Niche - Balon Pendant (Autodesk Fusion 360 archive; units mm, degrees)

design "Encalmo Grand" references "Encalmo Grand", "Niche - Chief Architect - Luxe Single Pendant Cordset", "Luxe Single Pendant Cordset - 4ft Standard"
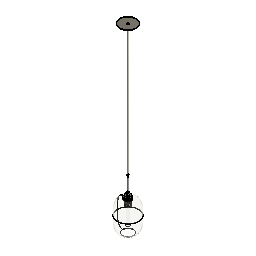
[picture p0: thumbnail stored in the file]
external_derived "ExternalDerived1" bodies "Encalmo Grand", "Encalmo Grand (1)"
external_derived "ExternalDerived2" bodies "Socket Body", "Shade Ring", "Shade Ring +Collar", "Socket", "Body1", "Metal Strain Relief", "Fabric Cord (1)", "Stem (Threaded)"
move "Move1"
external_derived "ExternalDerived3" bodies "T9-Bulb"
move "Move2"
scale "Scale1"
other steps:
derived_base_feature "Derived Base Feature1" bodies "Encalmo Grand", "Encalmo Grand (1)"
derived_base_feature "Derived Base Feature2" bodies "Socket Body", "Shade Ring", "Shade Ring +Collar", "Socket", "Body1", "Metal Strain Relief", "Fabric Cord (1)", "Stem (Threaded)"
derived_base_feature "Derived Base Feature3" bodies "T9-Bulb"
named bodies: "Encalmo Grand", "Encalmo Grand (1)", "Socket Body", "Shade Ring", "Shade Ring +Collar", "Socket", "Body1", "Metal Strain Relief", "Fabric Cord (1)", "Stem (Threaded)", "Cap (Threaded)", "5M Set Screw", "T9-Bulb"

design "Luxe Single Pendant Cordset - 4ft Standard" references "Luxe Canopy - Single Pendant Cordset"
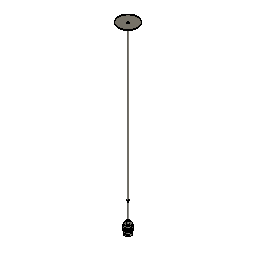
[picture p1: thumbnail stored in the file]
external_derived "ExternalDerived2" bodies "Cap (Threaded)"
move "Move1"
move "Move2"
offset_faces "OffsetFaces1" distance 1051.56
move "Move3"
move "Move4"
move "Move5"
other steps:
derived_base_feature "Derived Base Feature9" bodies "Socket Body", "Shade Ring", "Shade Ring +Collar", "Socket"
derived_base_feature "Derived Base Feature10" bodies "Body1"
derived_base_feature "Derived Base Feature12" bodies "Metal Strain Relief"
derived_base_feature "Derived Base Feature13" bodies "Fabric Cord (1)"
derived_base_feature "Derived Base Feature14" bodies "Stem (Threaded)"
derived_base_feature "Derived Base Feature15" bodies "Cap 9Threaded)", "Cap (Threaded)"
named bodies: "Socket Body", "Shade Ring", "Shade Ring +Collar", "Socket", "Metal Strain Relief", "Fabric Cord (1)", "Stem (Threaded)", "Cap 9Threaded)", "Body1", "Cap (Threaded)", "5M Set Screw"

design "Encalmo Grand" references "Niche_Encalmo_Grand_Single_Pendant"
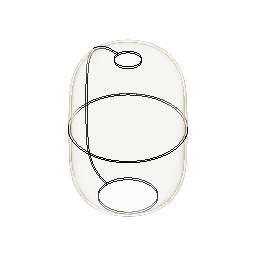
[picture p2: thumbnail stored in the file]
external_derived "ExternalDerived1" bodies "Encalmo Grand"
work_plane "WorkPlane1" AlongDistance -124.2212
split "Split1" bodies "Encalmo Grand (1)"
fillet "Fillet1" radius 0.0254
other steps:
derived_base_feature "Derived Base Feature" bodies "Encalmo Grand"
named bodies: "Encalmo Grand", "Encalmo Grand (1)"

design "Luxe Canopy - Single Pendant Cordset" references "Canopy Mounting Bar Screw", "Canopy Mounting Bar", "M5 Set Screw", "Plastic Strain Relief", "Luxe Cordset"
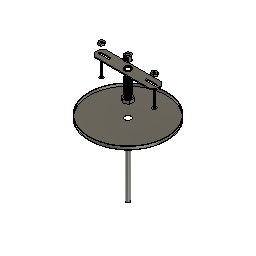
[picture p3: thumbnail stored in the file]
sketch "Sketch1" plane through (0, 0, 0) normal (0, 0, 1) x axis (1, 0, 0)
  circle C1 centre (0, 0) radius 63.5
  point P1 (0, 0)
  point P2 (0, 0)
  coincident P1 P2
  dimension "d1" diameter C1 = 127
extrude "Extrude1" new body sketch "Sketch1" along normal blind 5.08
shell "Shell1" innerThickness 0.762
hole "Hole1" HoleDepth 35.56 HoleDiameter 10.16 TipAngle 118
component_from_bodies "Body->Comp1"
component_insert "Component Insert1"
component_insert "Component Insert2"
component_insert "Component Insert3"
sketch "Sketch2" plane through (0, 0, 0) normal (0, 0, 1) x axis (1, 0, 0)
  circle C1 centre (0, 0) radius 3.175
  point P1 (0, 0)
  point P2 (0, 0)
  coincident P1 P2
  dimension "d8" diameter C1 = 6.35
extrude "Extrude2" new body sketch "Sketch2" along normal blind 127 and against normal blind 127 bodies "Fabric Cord"
component_insert "Component Insert4"
component_insert "Component Insert5"
position "Position1"
sketch "Sketch3" plane through (0, 0, 0.762) normal (0, 0, 1) x axis (-1, 0, 0)
  circle C1 centre (-0.0475, 0.2257) radius 5.08
  circle C2 centre (0, 0) radius 62.738
  circle C3 centre (0, 0) radius 4.826
  concentric C2 C3
  dimension "d13" diameter C3 = 9.652
extrude "Extrude3" new body sketch "Sketch3" profile of C3 along normal blind 25.4 bodies "Threaded Nipple"
shell "Shell2" innerThickness 1.27
thread "Thread1"
sketch "Sketch5" plane through (0, 0, 127) normal (0, 0, 1) x axis (-1, 0, 0)
  line L1 (-6.8191, 3.937) -> (0, 7.874)
  line L2 (-6.8191, -3.937) -> (-6.8191, 3.937)
  line L3 (0, -7.874) -> (-6.8191, -3.937)
  line L4 (6.8191, -3.937) -> (0, -7.874)
  line L5 (6.8191, 3.937) -> (6.8191, -3.937)
  line L6 (0, 7.874) -> (6.8191, 3.937)
  circle C1 centre (0, 0) radius 3.175
  point P2 (0, 0)
  point P9 (0, 0)
  point P3 (0, 7.874)
  coincident P2 P9
  dimension "d20" distance P3 P9 = 7.874
extrude "Extrude4" new body sketch "Sketch5" along normal blind 5.08 bodies "Hex Nut"
move "Move1"
thread "Thread2"
move "Move2" TranslateX 0 TranslateY 0 TranslateZ -55.88
move "Move3" TranslateX 0 TranslateY 0 TranslateZ 60.96
position "Position2"
sketch "Sketch6" plane through (0, 0, 0) normal (0, 0, 1) x axis (1, 0, 0)
  circle C1 centre (0, 0) radius 9.525
  point P1 (0, 0)
  point P2 (0, 0)
  coincident P1 P2
  dimension "d29" diameter C1 = 19.05
extrude "Extrude5" new body sketch "Sketch6" along normal blind 16.129 bodies "Metal Strain Relief"
move "Move4" TranslateX 0 TranslateY 0 TranslateZ -86.36
hole "Hole2" HoleDepth 10.16 HoleDiameter 5.08 TipAngle 118
hole "Hole3" HoleDepth 4.064 HoleDiameter 7.62 TipAngle 180
hole "Hole4" HoleDepth 12.192 HoleDiameter 9.144 TipAngle 180
thread "Thread3" ThreadOffset 0 ThreadLength 6.096
move "Move1" TranslateX 0 TranslateY 0 TranslateZ 68.58
move "Move5" TranslateX 0 TranslateY 0 TranslateZ 138.43
component_insert "Component Insert6"
external_derived "ExternalDerived1" bodies "5M Set Screw"
move "Move6" TranslateX 0 TranslateY 0 TranslateZ -185.42
copy_paste_bodies "CopyPasteBodies1"
move "Move7" TranslateX 0 TranslateY 0 TranslateZ -12.7
offset_faces "OffsetFaces1" distance -152.4
move "Move8"
component_from_bodies "Body->Comp2"
component_from_bodies "Body->Comp3"
component_from_bodies "Body->Comp4"
component_from_bodies "Body->Comp5"
hole "Hole1" HoleDepth 25.4 HoleDiameter 6.35 TipAngle 180
sketch "Sketch7" plane through (0, 0, 0) normal (0, 0, 1) x axis (1, 0, 0)
  line L1 (49.784, 3.9595) -> (52.07, 0)
  line L2 (45.212, 3.9595) -> (49.784, 3.9595)
  line L3 (42.926, 0) -> (45.212, 3.9595)
  line L4 (45.212, -3.9595) -> (42.926, 0)
  line L5 (49.784, -3.9595) -> (45.212, -3.9595)
  line L6 (52.07, 0) -> (49.784, -3.9595)
  point P2 (52.07, 0)
  point P8 (47.498, 0)
  dimension "d63" distance P2 P8 = 4.572
extrude "Extrude6" new body sketch "Sketch7" along normal blind 3.175 bodies "Mounting Hex Nut"
hole "Hole5" HoleDepth 25.4 HoleDiameter 3.81 TipAngle 180
thread "Thread4"
move "Move9"
component_from_bodies "Body->Comp6"
copy_paste "CopyPaste1"
move "Move10"
derived_base_feature "Derived Base Feature3" bodies "Stem (Threaded)", "Cap 9Threaded)"
move "Move11"
component_from_bodies "Body->Comp7"
component_from_bodies "Body->Comp8"
component_from_bodies "Body->Comp9"
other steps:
base_feature "Base Feature1"
base_feature "Base Feature1" bodies "Stem (Threaded)"
base_feature "Base Feature1" bodies "Cap 9Threaded)"
base_feature "Base Feature1" bodies "Fabric Cord"
base_feature "Base Feature1" bodies "Metal Strain Relief"
base_feature "Base Feature1" bodies "Mounting Hex Nut"
base_feature "Base Feature1" bodies "Hex Nut"
base_feature "Base Feature1" bodies "Fabric Cord (1)"
base_feature "Base Feature1" bodies "Threaded Nipple"
derived_base_feature "Derived Base Feature1" bodies "Socket Body", "Shade Ring", "Shade Ring +Collar", "Socket", "Rigid Stem"
derived_base_feature "Derived Base Feature2" bodies "5M Set Screw"
base_feature "Base Feature1" bodies "Fabric Cord", "Fabric Cord (1)"
create_component "CreateComponent1"
remove_body "RemoveBody1"
create_component "CreateComponent2"
remove_body "RemoveBody2"
create_component "CreateComponent3"
remove_body "RemoveBody3"
create_component "CreateComponent4"
remove_body "RemoveBody4"
create_component "CreateComponent5"
remove_body "RemoveBody5"
create_component "CreateComponent6"
remove_body "RemoveBody6"
create_component "CreateComponent7"
remove_body "RemoveBody7"
create_component "CreateComponent8"
remove_body "RemoveBody8"
create_component "CreateComponent9"
remove_body "RemoveBody9"
named bodies: "Fabric Cord", "Threaded Nipple", "Hex Nut", "Metal Strain Relief", "Socket Body", "Shade Ring", "Shade Ring +Collar", "Socket", "Rigid Stem", "5M Set Screw", "Fabric Cord (1)", "Mounting Hex Nut", "Stem (Threaded)", "Cap 9Threaded)"

design "M5 Set Screw"
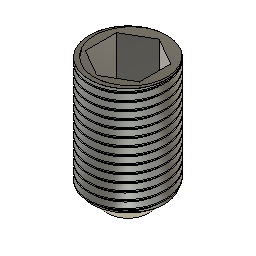
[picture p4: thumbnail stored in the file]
sketch "Sketch1" plane through (0, 0, 0) normal (0, 0, 1) x axis (1, 0, 0)
  circle C1 centre (0, 0) radius 2.5
  point P1 (0, 0)
  point P2 (0, 0)
  coincident P1 P2
  dimension "d1" diameter C1 = 5
extrude "Extrude1" new body sketch "Sketch1" along normal blind 8
sketch "Sketch2" plane through (0, 0, 8) normal (0, 0, 1) x axis (-1, 0, 0)
  line L1 (-1.7321, 1) -> (0, 2)
  line L2 (-1.7321, -1) -> (-1.7321, 1)
  line L3 (0, -2) -> (-1.7321, -1)
  line L4 (1.7321, -1) -> (0, -2)
  line L5 (1.7321, 1) -> (1.7321, -1)
  line L6 (0, 2) -> (1.7321, 1)
  circle C1 centre (0, 0) radius 2.5
  point P2 (0, 0)
  point P9 (0, 0)
  coincident P2 P9
extrude "Extrude2" cut sketch "Sketch2" profile of L1 L2 L3 L4 L5 L6 against normal blind 3
thread "Thread1" ThreadOffset 0.99 ThreadLength 7
chamfer "Chamfer1" distance 1.15

design "Luxe Cordset" references "M5 Set Screw"
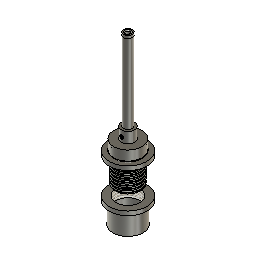
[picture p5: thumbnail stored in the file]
sketch "Sketch1" plane through (0, 0, 0) normal (0, 0, 1) x axis (1, 0, 0)
  circle C1 centre (0, 0) radius 20.6
  point P1 (0, 0)
  point P2 (0, 0)
  coincident P1 P2
  dimension "d11" diameter C1 = 41.2
extrude "Extrude1" new body sketch "Sketch1" along normal blind 14 bodies "Socket Body"
sketch "Sketch2" plane through (0, 0, 14) normal (0, 0, 1) x axis (-1, 0, 0)
  circle C1 centre (0, 0) radius 20.6
  circle C2 centre (0, 0) radius 9.6
  concentric C1 C2
  dimension "d3" diameter C2 = 19.2
extrude "Extrude2" add sketch "Sketch2" profile of C2 along normal blind 15.75
sketch "Sketch3" plane through (0, 0, 29.75) normal (0, 0, 1) x axis (-1, 0, 0)
  circle C1 centre (0, 0) radius 9.6
  circle C2 centre (0, 0) radius 5.75
  concentric C1 C2
  dimension "d6" diameter C2 = 11.5
extrude "Extrude3" new body sketch "Sketch3" profile of C2 along normal blind 114 bodies "Rigid Stem"
move "Move1"
sketch "Sketch4" plane through (0, 0, 203.75) normal (0, 0, 1) x axis (-1, 0, 0)
  circle C1 centre (0, 0) radius 5.75
  circle C2 centre (0, 0) radius 27.5
  dimension "d10" diameter C2 = 55
extrude "Extrude4" new body sketch "Sketch4" profile of C2 along normal blind 6 bodies "Shade Ring"
hole "Hole1" HoleDepth 25 HoleDiameter 42.75 TipAngle 118
sketch "Sketch5" plane through (0, 0, 0) normal (0, 0, 1) x axis (1, 0, 0)
  circle C1 centre (0, 0) radius 22
  point P1 (0, 0)
  point P2 (0, 0)
  coincident P1 P2
  dimension "d18" diameter C1 = 44
move "Move2"
copy_paste_bodies "CopyPasteBodies1"
move "Move3"
sketch "Sketch6" plane through (0, 0, 60) normal (0, 0, -1) x axis (1, 0, 0)
  circle C1 centre (0, 0) radius 20.6
  circle C2 centre (0, 0) radius 21.375
  circle C3 centre (0, 0) radius 20
  concentric C1 C2
  concentric C1 C3
  dimension "d21" diameter C2 = 42.75
  dimension "d24" diameter C3 = 40
cylinder_primitive "CylinderPrimitive1" Height 8 Diameter 42.75
thread "Thread1"
thread "Thread3"
hole "Hole2" HoleDepth 18 HoleDiameter 39 TipAngle 180
move "Move4"
move "Move5"
move "Move6"
hole "Hole3" HoleDepth 114 HoleDiameter 7.6 TipAngle 180
derived_base_feature "Derived Base Feature" bodies "Socket"
move "Move7"
scale "Scale1" ScaleX 1.2 ScaleY 1.2
move "Move8"
sketch "Sketch8" plane through (0, 0, -23.9827) normal (0, 0, -1) x axis (1, 0, 0)
  circle C1 centre (0, -0.036) radius 27.5
  circle C2 centre (0, -0.036) radius 22
  circle C3 centre (0, -0.036) radius 19.5
  dimension "d36" diameter C2 = 44
  dimension "d42" = -2.5
extrude "Extrude7" add sketch "Sketch8" profile of C2 C3 along normal blind 30
offset_faces "OffsetFaces1" distance 2.75
offset_faces "OffsetFaces2" distance -9
thread "Thread2"
move "Move9"
move "Move10"
move "Move11"
scale "Scale2" ScaleZ 1.2
move "Move12"
move "Move13"
move "Move14"
move "Move15"
move "Move16"
split_face "SplitFace1"
move "Move17"
move "Move18"
move "Move19"
move "Move20"
move "Move21"
move "Move22"
move "Move23"
move "Move24"
move "Move25"
move "Move26"
move "Move27"
thread "Thread4"
move "Move28"
move "Move29"
move "Move30"
hole "Hole4" HoleDepth 21 HoleDiameter 39.35 TipAngle 180
hole "Hole5" HoleDepth 9 HoleDiameter 5 TipAngle 180
move "Move31"
move "Move32"
hole "Hole6" HoleDepth 20 HoleDiameter 10 TipAngle 180
move_face "MoveFace3"
move "Move33"
move "Move34"
move "Move35"
move "Move36"
move "Move37"
thread "Thread5" ThreadOffset 0 ThreadLength 6
thread "Thread6" ThreadOffset 0 ThreadLength 6
move "Move38"
move "Move39"
move "Move40"
move "Move41"
component_insert "Component Insert"
thread "Thread7" ThreadOffset 0.5 ThreadLength 5.337
chamfer "Chamfer1" distance 0.5 distance 0.35
sketch "Sketch12" plane through (0, 0, 0) normal (0, 0, 1) x axis (1, 0, 0)
  circle C1 centre (0, 0) radius 6.35
  dimension "d60" diameter C1 = 12.7
extrude "Extrude8" new body sketch "Sketch12" along normal blind 115 bodies "Stem (Threaded)"
hole "Hole7" HoleDepth 115 HoleDiameter 9.65 TipAngle 118
thread "Thread8" ThreadOffset 0 ThreadLength 12.5
thread "Thread9" ThreadOffset 0 ThreadLength 12.5
sketch "Sketch13" plane through (0, 0, 0) normal (0, 0, 1) x axis (1, 0, 0)
  circle C1 centre (0, 0) radius 6.35
  point P1 (0, 0)
  point P2 (0, 0)
  coincident P1 P2
  dimension "d70" diameter C1 = 12.7
extrude "Extrude9" new body sketch "Sketch13" along normal blind 4 bodies "Cap 9Threaded)"
sketch "Sketch14" plane through (0, 0, 4) normal (0, 0, 1) x axis (-1, 0, 0)
  circle C1 centre (0, 0) radius 6.35
  circle C2 centre (0, 0) radius 4.5
  concentric C1 C2
  dimension "d73" diameter C2 = 9
extrude "Extrude10" add sketch "Sketch14" profile of C2 against normal blind 14
thread "Thread10"
hole "Hole8" HoleDepth 115 HoleDiameter 6.5 TipAngle 118 CSDiameter 9 CSAngle 90
move "Move42"
move "Move43"
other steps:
base_feature "Base Feature" bodies "Shade Ring +Collar"
named bodies: "Socket Body", "Shade Ring", "Shade Ring +Collar", "Socket", "Rigid Stem", "Stem (Threaded)", "Cap 9Threaded)"

design "Niche - Chief Architect - Luxe Single Pendant Cordset"
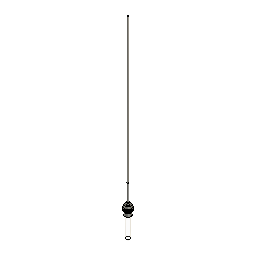
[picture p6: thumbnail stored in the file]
derived_base_feature "Derived Base Feature" bodies "Socket Body", "Shade Ring", "Shade Ring +Collar", "Socket", "Canopy", "Metal Strain Relief", "Fabric Cord (1)", "Stem (Threaded)"
remove_body "RemoveBody1"
remove_body "RemoveBody2"
split "Split1" bodies "Socket Body (1)"
remove_body "RemoveBody3"
align "Align1"
hole "Hole1" HoleDepth 19.05 HoleDiameter 8.89 TipAngle 118
combine "Combine1" bodies "Shade Ring"
split "Split2" bodies "Socket (1)"
remove_body "RemoveBody4"
split "Split3" bodies "Fabric Cord (1) (1)"
remove_body "RemoveBody5"
combine "Combine2" bodies "Socket Body"
align "Align2"
combine "Combine3" bodies "Metal Strain Relief"
sketch "Sketch1" plane through (0, 0, 0) normal (0, 1, 0) x axis (1, 0, 0)
  line L1 (13.1098, 24.9049) -> (-12.2902, 24.9049)
  line L2 (18.1898, 37.1766) -> (18.1898, 29.9849)
  line L3 (-17.3702, 29.9849) -> (-17.3702, 36.7132)
  line L4 (0, 132.969) -> (0, 24.9049)
  arc A1 centre (0, 86.36) radius 46.609 clockwise from (-22.6031, 45.5985) to (23.276, 45.979)
  arc A2 centre (-27.5302, 36.7132) radius 10.16 clockwise from (-22.6031, 45.5985) to (-17.3702, 36.7132)
  arc A3 centre (28.3498, 37.1766) radius 10.16 clockwise from (18.1898, 37.1766) to (23.276, 45.979)
  arc A4 centre (-12.2902, 29.9849) radius 5.08 clockwise from (-12.2902, 24.9049) to (-17.3702, 29.9849)
  arc A5 centre (13.1098, 29.9849) radius 5.08 clockwise from (18.1898, 29.9849) to (13.1098, 24.9049)
  point P5 (18.1898, 43.4469)
  point P3 (-17.3702, 24.9049)
  point P4 (18.1898, 24.9049)
  point P18 (0, 24.9049)
  point P19 (0, 132.969)
  horizontal L1
  vertical L2
  vertical L3
  tangent A1 A2
  tangent L3 A2
  coincident P5 L2
  coincident P5 A1
  tangent L2 A3
  tangent A1 A3
  equal A2 A3
  coincident P3 L1
  coincident P3 L3
  tangent L1 A4
  tangent L3 A4
  coincident P4 L1
  coincident P4 L2
  tangent L1 A5
  tangent L2 A5
  coincident L1 P18
  coincident A1 P19
  perpendicular L1 L4
  dimension "d4" diameter A1 = 93.218
  dimension "d5" distance P3 P4 = 35.56
  dimension "d6" distance P4 P5 = 18.542
  dimension "d7" radius A2 = 10.16
  dimension "d8" radius A4 = 5.08
  dimension "d9" radius A5 = 5.08
revolve "Revolve1" sketch "Sketch1" AlongAngle 360 bodies "G30-Bulb"
move "Move1"
sketch "Sketch2" plane through (0, 0, 0) normal (0, 1, 0) x axis (1, 0, 0)
  line L1 (12.7, 0) -> (-12.7, 0)
  line L2 (12.7, 152.4) -> (12.7, 0)
  line L3 (-12.7, 0) -> (-12.7, 152.4)
  line L4 (0, 165.1) -> (0, 0)
  arc A1 centre (0, 152.4) radius 12.7 clockwise from (-12.7, 152.4) to (12.7, 152.4)
  point P1 (0, 0)
  point P7 (0, 0)
  point P8 (0, 165.1)
  horizontal L1
  vertical L2
  vertical L3
  coincident P1 P7
  midpoint A1 P8
  perpendicular L1 L4
revolve "Revolve2" sketch "Sketch2" AlongAngle 360 bodies "T9-Bulb"
move "Move2"
sketch "Sketch3" plane through (0, 0, 0) normal (0, 1, 0) x axis (1, 0, 0)
  line L1 (12.7, 0) -> (-12.7, 0)
  line L2 (12.7, 254) -> (12.7, 0)
  line L3 (-12.7, 0) -> (-12.7, 254)
  line L4 (0, 266.7) -> (0, 0)
  arc A1 centre (0, 254) radius 12.7 clockwise from (-12.7, 254) to (12.7, 254)
  point P1 (0, 0)
  point P7 (0, 0)
  point P8 (0, 266.7)
  horizontal L1
  vertical L2
  vertical L3
  coincident P1 P7
  midpoint A1 P8
  perpendicular L1 L4
revolve "Revolve3" sketch "Sketch3" AlongAngle 360 bodies "T8-Bulb"
move "Move3"
move "Move4"
move "Move5"
sketch "Sketch4" plane through (0, 0, 0) normal (0, 1, 0) x axis (1, 0, 0)
  line L1 (15.875, -8.763) -> (-15.875, -8.763)
  line L2 (15.875, 22.987) -> (15.875, -8.763)
  line L3 (-15.875, 22.987) -> (15.875, 22.987)
  line L4 (-15.875, -8.763) -> (-15.875, 22.987)
  line L5 (0, 22.987) -> (0, -8.763)
  point P6 (0, -8.763)
  point P7 (0, 22.987)
  point P2 (-15.875, -8.763)
  point P3 (15.875, -8.763)
  point P5 (-15.875, 22.987)
  horizontal L1
  vertical L2
  horizontal L3
  vertical L4
  midpoint L1 P6
  midpoint L3 P7
  dimension "d13" distance P2 P3 = 31.75
  dimension "d14" distance P2 P5 = 31.75
revolve "Revolve4" sketch "Sketch4" AlongAngle 360 bodies "Bulb Extender"
move "Move6"
sketch "Sketch5" plane through (0, 0, 0) normal (0, 1, 0) x axis (1, 0, 0)
  line L1 (-12.7, 35.56) -> (12.7, 35.56)
  line L2 (-12.7, 5.08) -> (-12.7, 35.56)
  line L3 (12.7, 5.08) -> (-12.7, 5.08)
  line L4 (12.7, 35.56) -> (12.7, 5.08)
  line L5 (-12.7, 5.08) -> (12.7, 35.56)
  line L6 (12.7, 5.08) -> (-12.7, 35.56)
  line L7 (0, 35.56) -> (0, 5.08)
  point P6 (0, 20.32)
  point P7 (0, 5.08)
  point P8 (0, 35.56)
  horizontal L1
  perpendicular L1 L2
  parallel L1 L3
  parallel L2 L4
  coincident L5 P6
  coincident L6 P6
  midpoint L3 P7
  midpoint L1 P8
revolve "Revolve5" sketch "Sketch5" AlongAngle 360 bodies "Y-Spliter"
sketch "Sketch6" plane through (0, 0, 0) normal (0, 1, 0) x axis (1, 0, 0)
  line L1 (-55.88, 64.9514) -> (-21.59, 64.9514)
  line L2 (-55.88, 35.7414) -> (-55.88, 64.9514)
  line L3 (-21.59, 35.7414) -> (-55.88, 35.7414)
  line L4 (-21.59, 64.9514) -> (-21.59, 35.7414)
  line L5 (-55.88, 35.7414) -> (-21.59, 64.9514)
  line L6 (-21.59, 35.7414) -> (-55.88, 64.9514)
  line L7 (-38.735, 64.9514) -> (-38.735, 35.7414)
  point P6 (-38.735, 50.3464)
  point P7 (-38.735, 35.7414)
  point P8 (-38.735, 64.9514)
  point P4 (-55.88, 35.7414)
  point P5 (-21.59, 35.7414)
  point P2 (-21.59, 64.9514)
  horizontal L1
  perpendicular L1 L2
  parallel L1 L3
  parallel L2 L4
  coincident L5 P6
  coincident L6 P6
  midpoint L3 P7
  midpoint L1 P8
  dimension "d17" distance P4 P5 = 34.29
  dimension "d18" distance P2 P5 = 29.21
revolve "Revolve6" sketch "Sketch6" AlongAngle 360
chamfer "Chamfer1" distance 7.62
move "Move7"
mirror "Mirror1" mirrorStitchTolerance 0.1016
move "Move8"
combine "Combine4"
move "Move9"
sketch "Sketch7" plane through (0, 0, 0) normal (0, 1, 0) x axis (1, 0, 0)
  line L1 (-15.24, 40.64) -> (-15.24, 48.1816)
  line L2 (12.7, 38.1) -> (-12.7, 38.1)
  line L3 (15.24, 48.1816) -> (15.24, 40.64)
  line L4 (0, 100.1623) -> (0, 38.1)
  arc A1 centre (0, 76.2) radius 23.9623 clockwise from (-19.7282, 62.5988) to (19.7282, 62.5988)
  arc A2 centre (-40.64, 48.1816) radius 25.4 clockwise from (-19.7282, 62.5988) to (-15.24, 48.1816)
  arc A3 centre (40.64, 48.1816) radius 25.4 clockwise from (15.24, 48.1816) to (19.7282, 62.5988)
  arc A4 centre (-12.7, 40.64) radius 2.54 clockwise from (-12.7, 38.1) to (-15.24, 40.64)
  arc A5 centre (12.7, 40.64) radius 2.54 clockwise from (15.24, 40.64) to (12.7, 38.1)
  point P15 (0, 38.1)
  point P16 (0, 100.1623)
  parallel L1 L3
  tangent A1 A2
  tangent L1 A2
  tangent A1 A3
  tangent L3 A3
  tangent L1 A4
  tangent L2 A4
  tangent L2 A5
  tangent L3 A5
  midpoint L2 P15
  midpoint A1 P16
  perpendicular L2 L4
  dimension "d23" radius A2 = 25.4
  dimension "d24" radius A3 = 25.4
  dimension "d25" radius A4 = 2.54
  dimension "d26" radius A5 = 2.54
revolve "Revolve7" sketch "Sketch7" AlongAngle 360 bodies "A15-Bulb"
move "Move10"
copy_paste_bodies "CopyPasteBodies1"
copy_paste_bodies "CopyPasteBodies2"
move "Move11"
mirror "Mirror2" mirrorStitchTolerance 0.1016 bodies "A15-Bulb (1) (1)"
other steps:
base_feature "Base Feature1" bodies "Y-Spliter", "Bulb Extender", "Y-Spliter (1)", "Bulb Extender (1)"
base_feature "Base Feature2" bodies "A15-Bulb", "A15-Bulb (1)"
named bodies: "Socket Body", "Shade Ring", "Shade Ring +Collar", "Socket", "Canopy", "Metal Strain Relief", "Fabric Cord (1)", "Stem (Threaded)", "Adapter", "5M Set Screw", "Body1 (1)", "Socket Body (1)", "Socket (1)", "Fabric Cord (1) (1)", "G30-Bulb", "T9-Bulb", "T8-Bulb", "Bulb Extender", "Y-Spliter", "A15-Bulb", "Y-Spliter (1)", "Bulb Extender (1)", "A15-Bulb (1)", "A15-Bulb (1) (1)"

design "Plastic Strain Relief"
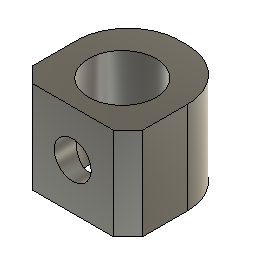
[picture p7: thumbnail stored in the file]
base_feature "Base Feature" bodies "strainrelief"
named bodies: "strainrelief"

design "Canopy Mounting Bar Screw"
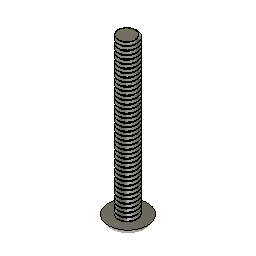
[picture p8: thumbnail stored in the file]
base_feature "Base Feature" bodies "screw1"
named bodies: "screw1"

design "Canopy Mounting Bar"
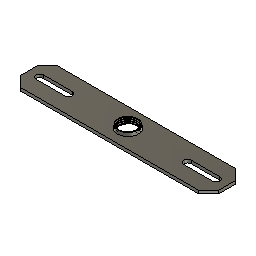
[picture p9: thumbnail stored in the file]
base_feature "Base Feature" bodies "mountingbar"
named bodies: "mountingbar"

design "Niche_Encalmo_Grand_Single_Pendant"
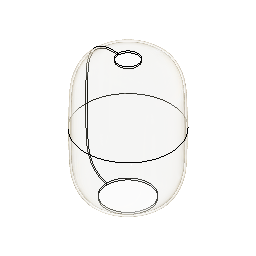
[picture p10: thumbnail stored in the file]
